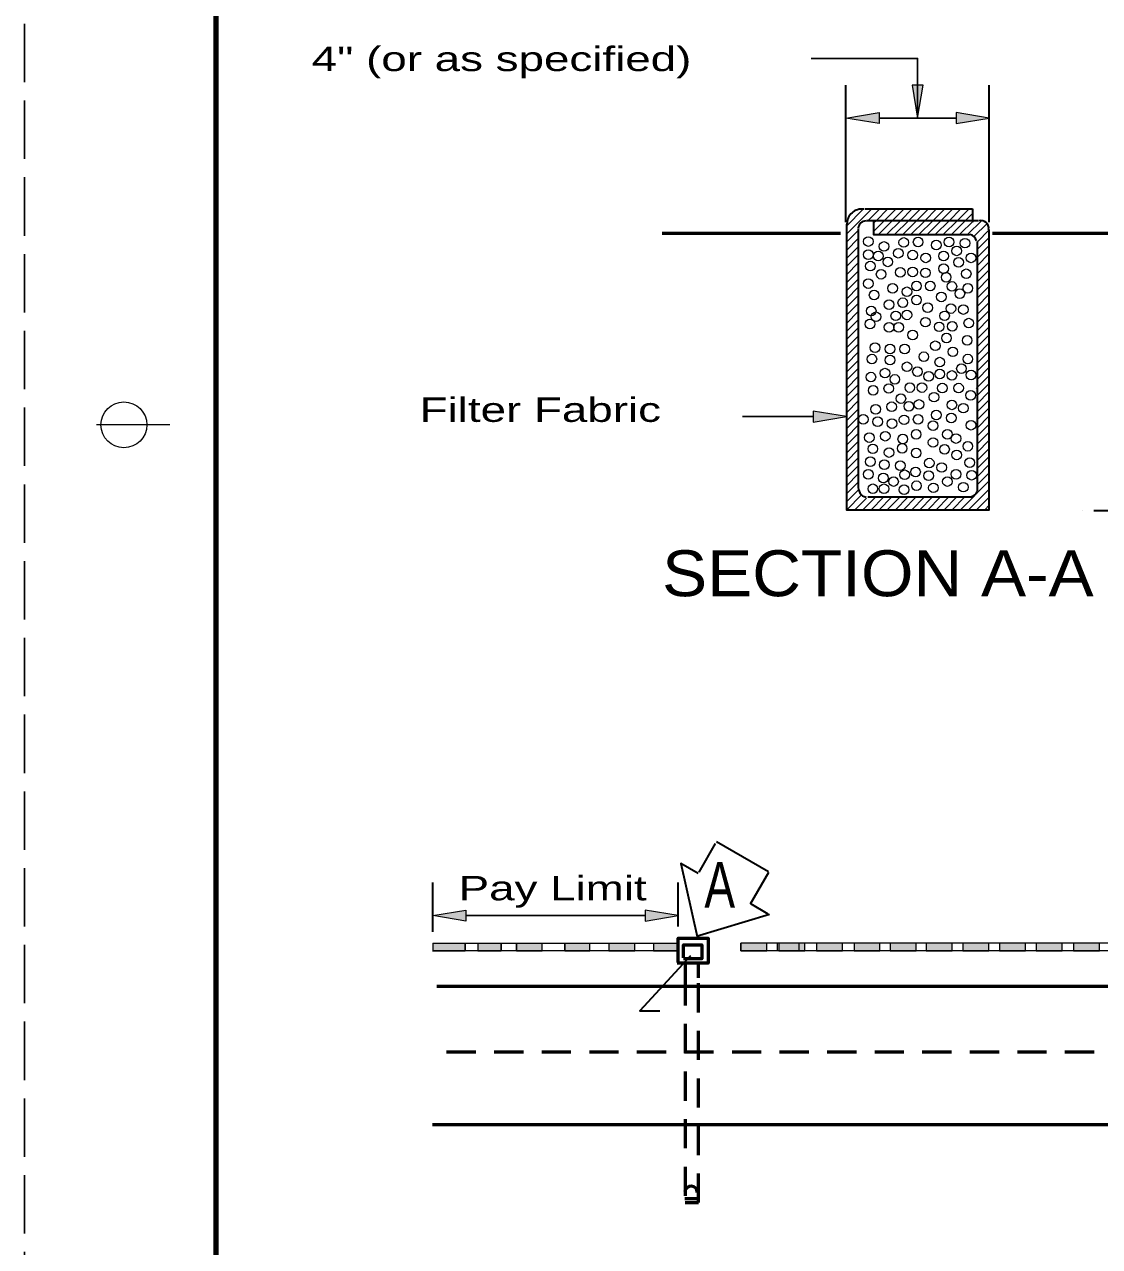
# Model space of a CAD drawing. Extents: x 36 to 71.3, y 0.3 to 22.3.
# Drawn here: x 37.55 to 43.4, y 10.65 to 17.3 of the extents above; entities that cross this region are included whole.
import ezdxf

# ---------------------------------------------------------------- set-up
doc = ezdxf.new("R2010")
doc.units = 0
doc.header["$LTSCALE"] = 0.053
doc.linetypes.add('LONG_DASHED', pattern=[7.5, 6, -1.5])
doc.linetypes.add('MEDIUM_DASHED', pattern=[4.5, 3, -1.5])
for name, color, linetype, lineweight in [('1', 7, 'Continuous', 13), ('2', 7, 'Continuous', 13), ('3', 7, 'MEDIUM_DASHED', 53), ('4', 7, 'Continuous', 13)]:
    doc.layers.add(name, color=color, linetype=linetype, lineweight=lineweight)

msp = doc.modelspace()

# ---------------------------------------------------------------- hatches: boundary and pattern name
at = {"layer": '1'}
for points in [[(42.20192, 16.82442), (42.20192, 16.76442), (42.02192, 16.79442), (42.02192, 16.79442)], [(42.62242, 16.82442), (42.62242, 16.76442), (42.80242, 16.79442), (42.80242, 16.79442)], [(39.95242, 12.48133), (39.95242, 12.42133), (39.77242, 12.45133), (39.77242, 12.45133)], [(40.92883, 12.48133), (40.92883, 12.42133), (41.10883, 12.45133), (41.10883, 12.45133)], [(39.77242, 12.25717), (39.94733, 12.25883), (39.94733, 12.3), (39.77242, 12.3)], [(40.01675, 12.25883), (40.14333, 12.25883), (40.14333, 12.3), (40.01675, 12.29758)], [(40.227, 12.25883), (40.36683, 12.25883), (40.36683, 12.3), (40.227, 12.3)], [(40.49008, 12.25883), (40.62658, 12.25883), (40.62658, 12.3), (40.49008, 12.3)], [(40.73117, 12.25883), (40.87208, 12.25883), (40.87208, 12.3), (40.73117, 12.3)], [(40.97333, 12.25883), (41.10658, 12.25883), (41.10658, 12.3), (40.97333, 12.3)], [(41.4495, 12.25992), (41.59092, 12.25992), (41.59092, 12.30192), (41.4495, 12.30192)], [(41.65583, 12.25992), (41.79725, 12.25992), (41.79725, 12.30192), (41.65583, 12.30192)], [(41.86217, 12.25992), (42.00358, 12.25992), (42.00358, 12.30192), (41.86217, 12.30192)], [(42.06558, 12.25992), (42.20692, 12.25992), (42.20692, 12.30192), (42.06558, 12.30192)], [(42.26183, 12.25992), (42.40325, 12.25992), (42.40325, 12.30192), (42.26183, 12.30192)], [(42.45817, 12.25992), (42.5995, 12.25992), (42.5995, 12.30192), (42.45817, 12.30192)], [(42.658, 12.25992), (42.79933, 12.25992), (42.79933, 12.30192), (42.658, 12.30192)], [(42.85783, 12.25992), (42.99925, 12.25992), (42.99925, 12.30192), (42.85783, 12.30192)], [(43.05758, 12.25992), (43.19908, 12.25992), (43.19908, 12.30192), (43.05758, 12.30192)], [(43.26092, 12.25992), (43.40242, 12.25992), (43.40242, 12.30192), (43.26092, 12.30192)]]:
    msp.add_hatch(color=256, dxfattribs=at).paths.add_polyline_path(points)
at = {"layer": '2'}
for points in [[(42.44217, 16.97442), (42.38217, 16.97442), (42.41217, 16.79442), (42.41217, 16.79442)], [(41.84392, 15.19867), (41.84392, 15.13867), (42.02383, 15.16867), (42.02383, 15.16867)]]:
    msp.add_hatch(color=256, dxfattribs=at).paths.add_polyline_path(points)

# ---------------------------------------------------------------- linework, layer by layer
at = {"layer": '1', "linetype": 'LONG_DASHED', "lineweight": 25}
msp.add_line((37.54825, 22.32408), (37.54825, 0.32408), dxfattribs=at)
at = {"layer": '1', "lineweight": 158}
msp.add_line((38.58992, 21.82408), (38.58992, 0.82408), dxfattribs=at)
at = {"layer": '1', "lineweight": 35}
for p, q in [((42.02192, 16.227), (42.02192, 16.97442)), ((42.80242, 16.227), (42.80242, 16.97442)), ((42.71142, 16.29858), (42.12467, 16.29858)), ((42.71142, 16.29983), (42.71142, 16.22733)), ((42.08992, 14.793), (42.08992, 16.19292)), ((42.13508, 16.2375), (42.74092, 16.2375)), ((42.73575, 16.12292), (42.73575, 14.76117)), ((42.70625, 14.72942), (42.14025, 14.72942)), ((43.37108, 14.658), (43.65075, 14.658)), ((41.5995, 12.6905), (41.31683, 12.85367)), ((41.31, 12.8435), (41.22008, 12.68775)), ((41.50267, 12.51567), (41.60258, 12.68875)), ((39.77242, 12.3625), (39.77242, 12.63133)), ((41.10883, 12.39142), (41.10883, 12.63133)), ((41.59883, 12.46008), (41.50417, 12.51475)), ((41.20808, 12.33892), (41.60467, 12.45967))]:
    msp.add_line(p, q, dxfattribs=at)
at = {"layer": '1', "lineweight": 25}
for p, q in [((42.20192, 16.79442), (42.62242, 16.79442)), ((42.73575, 15.94617), (42.80167, 16.01217)), ((39.95242, 12.45133), (40.92883, 12.45133))]:
    msp.add_line(p, q, dxfattribs=at)
at = {"layer": '1'}
for p, q in [((42.02392, 16.20667), (42.11625, 16.29892)), ((42.02392, 16.16242), (42.16008, 16.29858)), ((42.14317, 16.2375), (42.20425, 16.29858)), ((42.18742, 16.2375), (42.2485, 16.29858)), ((42.23158, 16.2375), (42.29267, 16.29858)), ((42.27575, 16.2375), (42.33683, 16.29858)), ((42.32, 16.2375), (42.38108, 16.29858)), ((42.36417, 16.2375), (42.42525, 16.29858)), ((42.40833, 16.2375), (42.46942, 16.29858)), ((42.45258, 16.2375), (42.51367, 16.29858)), ((42.49675, 16.2375), (42.55783, 16.29858)), ((42.54092, 16.2375), (42.602, 16.29858)), ((42.58517, 16.2375), (42.64625, 16.29858)), ((42.62933, 16.2375), (42.69042, 16.29858)), ((42.6735, 16.2375), (42.71142, 16.27542)), ((42.02392, 16.11825), (42.08992, 16.18425)), ((42.1715, 16.17742), (42.23158, 16.2375)), ((42.1715, 16.22158), (42.18742, 16.2375)), ((42.19817, 16.15983), (42.27575, 16.2375)), ((42.24233, 16.15983), (42.32, 16.2375)), ((42.2865, 16.15983), (42.36417, 16.2375)), ((42.33075, 16.15983), (42.40833, 16.2375)), ((42.37492, 16.15983), (42.45258, 16.2375)), ((42.41908, 16.15983), (42.49675, 16.2375)), ((42.46333, 16.15983), (42.54092, 16.2375)), ((42.5075, 16.15983), (42.58517, 16.2375)), ((42.55167, 16.15983), (42.62933, 16.2375)), ((42.59592, 16.15983), (42.6735, 16.2375)), ((42.64008, 16.15983), (42.71767, 16.2375)), ((42.68425, 16.15983), (42.76108, 16.23667)), ((42.68425, 16.15983), (42.76108, 16.23667)), ((42.71142, 16.23125), (42.71767, 16.2375)), ((42.7185, 16.14992), (42.79008, 16.22142)), ((42.7185, 16.14992), (42.79008, 16.22142)), ((42.73575, 16.1195), (42.80167, 16.18542)), ((42.02392, 16.07408), (42.08992, 16.14)), ((42.73575, 16.07875), (42.80167, 16.14475)), ((42.02392, 16.02983), (42.08992, 16.09583)), ((42.02392, 15.98567), (42.08992, 16.05167)), ((42.73575, 16.03458), (42.80167, 16.1005)), ((42.73575, 15.99033), (42.80167, 16.05633)), ((42.02392, 15.9415), (42.08992, 16.00742)), ((42.02392, 15.89725), (42.08992, 15.96325)), ((42.02392, 15.85308), (42.08992, 15.91908)), ((42.73575, 15.902), (42.80167, 15.96792)), ((42.73575, 15.85775), (42.80167, 15.92375)), ((42.02392, 15.80892), (42.08992, 15.87483)), ((42.73575, 15.81358), (42.80167, 15.87958)), ((42.02392, 15.76467), (42.08992, 15.83067)), ((42.02392, 15.7205), (42.08992, 15.7865)), ((42.73575, 15.76942), (42.80167, 15.83533)), ((42.73575, 15.72517), (42.80167, 15.79117)), ((42.02392, 15.67633), (42.08992, 15.74225)), ((42.73575, 15.681), (42.80167, 15.747)), ((42.02392, 15.63208), (42.08992, 15.69808)), ((42.02392, 15.58792), (42.08992, 15.65392)), ((42.73575, 15.63683), (42.80167, 15.70275)), ((42.73575, 15.59258), (42.80167, 15.65858)), ((42.02392, 15.54375), (42.08992, 15.60967)), ((42.73575, 15.54842), (42.80167, 15.61442)), ((42.02392, 15.4995), (42.08992, 15.5655)), ((42.02392, 15.45533), (42.08992, 15.52133)), ((42.73575, 15.50425), (42.80167, 15.57017)), ((42.73575, 15.46), (42.80167, 15.526)), ((42.02392, 15.41117), (42.08992, 15.47708)), ((42.73575, 15.41583), (42.80167, 15.48183)), ((42.02392, 15.36692), (42.08992, 15.43292)), ((42.02392, 15.32275), (42.08992, 15.38875)), ((42.7305, 15.32217), (42.80167, 15.39342)), ((42.73575, 15.37167), (42.80167, 15.43758)), ((42.02392, 15.27858), (42.08992, 15.3445)), ((42.73575, 15.28325), (42.80167, 15.34925)), ((42.02392, 15.23433), (42.08992, 15.30033)), ((42.02392, 15.19017), (42.08992, 15.25617)), ((42.73575, 15.23908), (42.80167, 15.305)), ((42.73575, 15.19483), (42.80167, 15.26083)), ((42.02392, 15.146), (42.08992, 15.21192)), ((42.73575, 15.15067), (42.80167, 15.21667)), ((38.33992, 15.12408), (37.93992, 15.12408)), ((42.02392, 15.10175), (42.08992, 15.16775)), ((42.02392, 15.05758), (42.08992, 15.12358)), ((42.73575, 15.1065), (42.80167, 15.17242)), ((42.73575, 15.06225), (42.80167, 15.12825)), ((42.02392, 15.01342), (42.08992, 15.07933)), ((42.73575, 15.01808), (42.80167, 15.08408)), ((42.02392, 14.96917), (42.08992, 15.03517)), ((42.02392, 14.925), (42.08992, 14.991)), ((42.73575, 14.97392), (42.80167, 15.03983)), ((42.73575, 14.92967), (42.80167, 14.99567)), ((42.02392, 14.88083), (42.08992, 14.94675)), ((42.73575, 14.8855), (42.80167, 14.9515)), ((42.02392, 14.83658), (42.08992, 14.90258)), ((42.02392, 14.79242), (42.08992, 14.85842)), ((42.73575, 14.84133), (42.80167, 14.90725)), ((42.73575, 14.79708), (42.80167, 14.86308)), ((42.02392, 14.74825), (42.08992, 14.81417)), ((42.64475, 14.66192), (42.80167, 14.81892)), ((42.02392, 14.704), (42.09, 14.77017)), ((42.026, 14.66192), (42.10692, 14.74283)), ((42.07025, 14.66192), (42.13367, 14.72533)), ((42.11442, 14.66192), (42.18192, 14.72942)), ((42.15858, 14.66192), (42.22608, 14.72942)), ((42.20283, 14.66192), (42.27025, 14.72942)), ((42.247, 14.66192), (42.3145, 14.72942)), ((42.29117, 14.66192), (42.35867, 14.72942)), ((42.33542, 14.66192), (42.40283, 14.72942)), ((42.37958, 14.66192), (42.44708, 14.72942)), ((42.42375, 14.66192), (42.49125, 14.72942)), ((42.468, 14.66192), (42.53542, 14.72942)), ((42.51217, 14.66192), (42.57958, 14.72942)), ((42.55633, 14.66192), (42.62383, 14.72942)), ((42.60058, 14.66192), (42.668, 14.72942)), ((42.68892, 14.66192), (42.80167, 14.77467)), ((42.73317, 14.66192), (42.80167, 14.7305)), ((42.77733, 14.66192), (42.80167, 14.68633)), ((39.94908, 12.25892), (39.94908, 12.30092)), ((40.0185, 12.25892), (40.0185, 12.30092)), ((40.14525, 12.25892), (40.14525, 12.30092)), ((40.22858, 12.25892), (40.22858, 12.30092)), ((40.3675, 12.25892), (40.3675, 12.30092)), ((40.49075, 12.25892), (40.49075, 12.30092)), ((40.62792, 12.25892), (40.62792, 12.30092)), ((40.73208, 12.25892), (40.73208, 12.30092)), ((40.87267, 12.25892), (40.87267, 12.30092)), ((40.97517, 12.25892), (40.97517, 12.30092)), ((44.00117, 12.26017), (41.44908, 12.26017)), ((41.44958, 12.25892), (41.44958, 12.30092)), ((43.99767, 12.30217), (41.45258, 12.30217)), ((41.59075, 12.25892), (41.59075, 12.30092)), ((41.64983, 12.25892), (41.64983, 12.30092)), ((41.767, 12.25892), (41.767, 12.30092))]:
    msp.add_line(p, q, dxfattribs=at)
at = {"layer": '1', "lineweight": 53}
for p, q in [((41.0205, 16.16875), (41.99267, 16.16875)), ((42.81908, 16.16875), (43.91108, 16.16875)), ((39.79458, 12.068), (49.87267, 12.068)), ((39.77025, 11.31333), (49.87267, 11.31333)), ((41.1435, 10.91117), (41.21817, 10.91117)), ((41.147, 10.88825), (41.21817, 10.88825))]:
    msp.add_line(p, q, dxfattribs=at)
at = {"layer": '1'}
for points in [[(42.20192, 16.82442), (42.20192, 16.76442), (42.02192, 16.79442), (42.02192, 16.79442)], [(42.62242, 16.82442), (42.62242, 16.76442), (42.80242, 16.79442), (42.80242, 16.79442)], [(39.95242, 12.48133), (39.95242, 12.42133), (39.77242, 12.45133), (39.77242, 12.45133)], [(40.92883, 12.48133), (40.92883, 12.42133), (41.10883, 12.45133), (41.10883, 12.45133)], [(39.77242, 12.25717), (39.94733, 12.25883), (39.94733, 12.3), (39.77242, 12.3)], [(40.01675, 12.25883), (40.14333, 12.25883), (40.14333, 12.3), (40.01675, 12.29758)], [(40.227, 12.25883), (40.36683, 12.25883), (40.36683, 12.3), (40.227, 12.3)], [(40.49008, 12.25883), (40.62658, 12.25883), (40.62658, 12.3), (40.49008, 12.3)], [(40.73117, 12.25883), (40.87208, 12.25883), (40.87208, 12.3), (40.73117, 12.3)], [(40.97333, 12.25883), (41.10658, 12.25883), (41.10658, 12.3), (40.97333, 12.3)], [(41.4495, 12.25992), (41.59092, 12.25992), (41.59092, 12.30192), (41.4495, 12.30192)], [(41.65583, 12.25992), (41.79725, 12.25992), (41.79725, 12.30192), (41.65583, 12.30192)], [(41.86217, 12.25992), (42.00358, 12.25992), (42.00358, 12.30192), (41.86217, 12.30192)], [(42.06558, 12.25992), (42.20692, 12.25992), (42.20692, 12.30192), (42.06558, 12.30192)], [(42.26183, 12.25992), (42.40325, 12.25992), (42.40325, 12.30192), (42.26183, 12.30192)], [(42.45817, 12.25992), (42.5995, 12.25992), (42.5995, 12.30192), (42.45817, 12.30192)], [(42.658, 12.25992), (42.79933, 12.25992), (42.79933, 12.30192), (42.658, 12.30192)], [(42.85783, 12.25992), (42.99925, 12.25992), (42.99925, 12.30192), (42.85783, 12.30192)], [(43.05758, 12.25992), (43.19908, 12.25992), (43.19908, 12.30192), (43.05758, 12.30192)], [(43.26092, 12.25992), (43.40242, 12.25992), (43.40242, 12.30192), (43.26092, 12.30192)]]:
    msp.add_lwpolyline(points, close=True, dxfattribs=at)
at = {"layer": '1', "lineweight": 35}
for points in [[(42.02392, 16.21717), (42.02392, 14.66192), (42.80167, 14.66192), (42.80167, 16.18783)], [(42.1715, 16.23242), (42.1715, 16.15983), (42.69408, 16.15983)], [(41.21692, 12.68058), (41.12225, 12.73525), (41.21175, 12.33825)], [(41.17475, 12.23217), (40.89875, 11.93308), (41.00808, 11.93308)]]:
    msp.add_lwpolyline(points, dxfattribs=at)
at = {"layer": '1', "lineweight": 53}
for points in [[(41.10883, 12.19525), (41.10883, 12.32892), (41.272, 12.32892), (41.272, 12.19275), (41.10183, 12.19275)], [(41.13658, 12.22075), (41.13658, 12.292), (41.23725, 12.292), (41.23725, 12.21567), (41.13658, 12.21567)]]:
    msp.add_lwpolyline(points, dxfattribs=at)
at = {"layer": '1'}
msp.add_lwpolyline([(41.10183, 12.25892), (39.77375, 12.25892), (39.77375, 12.30092), (41.10708, 12.30092)], dxfattribs=at)
for centre, radius in [((42.14375, 16.12233), 0.02615), ((42.22883, 16.09558), 0.02615), ((42.33642, 16.11725), 0.02615), ((42.41458, 16.11975), 0.02615), ((42.5135, 16.10325), 0.02615), ((42.58292, 16.11975), 0.02615), ((42.66975, 16.11342), 0.02615), ((42.14375, 16.05108), 0.02615), ((42.19758, 16.04342), 0.02615), ((42.30692, 16.05867), 0.02615), ((42.385, 16.0485), 0.02615), ((42.45625, 16.03325), 0.02615), ((42.55342, 16.04342), 0.02615), ((42.62458, 16.07142), 0.02615), ((42.70275, 16.03325), 0.02615), ((42.15417, 15.98867), 0.02615), ((42.24967, 16.01158), 0.02615), ((42.31733, 15.95433), 0.02615), ((42.385, 15.95683), 0.02615), ((42.4545, 15.95175), 0.02615), ((42.55342, 15.97467), 0.02615), ((42.635, 16.00908), 0.02615), ((42.14375, 15.89325), 0.02615), ((42.21317, 15.94417), 0.02615), ((42.40583, 15.8805), 0.02615), ((42.4805, 15.8805), 0.02615), ((42.56733, 15.92758), 0.02615), ((42.67667, 15.94667), 0.02615), ((42.175, 15.83083), 0.02615), ((42.27567, 15.86775), 0.02615), ((42.35375, 15.84867), 0.02615), ((42.54125, 15.82067), 0.02615), ((42.59858, 15.878), 0.02615), ((42.642, 15.8385), 0.02615), ((42.68542, 15.86775), 0.02615), ((42.25658, 15.77867), 0.02615), ((42.33125, 15.78892), 0.02615), ((42.40583, 15.80417), 0.02615), ((42.46667, 15.76217), 0.02615), ((42.59333, 15.75708), 0.02615), ((42.66108, 15.752), 0.02615), ((42.15933, 15.74433), 0.02615), ((42.18542, 15.7125), 0.02615), ((42.293, 15.71758), 0.02615), ((42.35375, 15.72267), 0.02615), ((42.4545, 15.68325), 0.02615), ((42.55867, 15.71758), 0.02615), ((42.15242, 15.67308), 0.02615), ((42.25658, 15.65525), 0.02615), ((42.30867, 15.65525), 0.02615), ((42.52917, 15.65783), 0.02615), ((42.60033, 15.66033), 0.02615), ((42.69058, 15.67817), 0.02615), ((42.385, 15.61325), 0.02615), ((42.50833, 15.55467), 0.02615), ((42.56908, 15.59667), 0.02615), ((42.68192, 15.584), 0.02615), ((42.16283, 15.48217), 0.02615), ((42.18017, 15.5445), 0.02615), ((42.26175, 15.53692), 0.02615), ((42.34167, 15.53692), 0.02615), ((42.44583, 15.49492), 0.02615), ((42.60375, 15.52158), 0.02615), ((42.68542, 15.48217), 0.02615), ((42.26175, 15.47708), 0.02615), ((42.35375, 15.44017), 0.02615), ((42.53258, 15.46558), 0.02615), ((42.65067, 15.43), 0.02615), ((42.15758, 15.38417), 0.02615), ((42.234, 15.40583), 0.02615), ((42.28783, 15.37142), 0.02615), ((42.41108, 15.41342), 0.02615), ((42.47183, 15.388), 0.02615), ((42.53258, 15.40075), 0.02615), ((42.59858, 15.39308), 0.02615), ((42.70275, 15.39558), 0.02615), ((42.16975, 15.31167), 0.02615), ((42.25483, 15.32183), 0.02615), ((42.36942, 15.32692), 0.02615), ((42.43542, 15.32692), 0.02615), ((42.5465, 15.32433), 0.02615), ((42.635, 15.32433), 0.02615), ((42.701, 15.28492), 0.02615), ((38.08992, 15.12408), 0.125), ((42.2705, 15.22258), 0.02615), ((42.32083, 15.26708), 0.02615), ((42.36425, 15.22508), 0.02615), ((42.41975, 15.23525), 0.02615), ((42.50133, 15.27475), 0.02615), ((42.59858, 15.23275), 0.02615), ((42.66108, 15.21492), 0.02615), ((42.11592, 15.15383), 0.02615), ((42.18367, 15.20858), 0.02615), ((42.33817, 15.15125), 0.02615), ((42.41458, 15.15383), 0.02615), ((42.5135, 15.178), 0.02615), ((42.59508, 15.16142), 0.02615), ((42.19408, 15.14108), 0.02615), ((42.27217, 15.13092), 0.02615), ((42.49617, 15.11942), 0.02615), ((42.70275, 15.122), 0.02615), ((42.14892, 15.05458), 0.02615), ((42.23575, 15.06217), 0.02615), ((42.33125, 15.04692), 0.02615), ((42.40417, 15.07233), 0.02615), ((42.49617, 15.02783), 0.02615), ((42.57425, 15.07233), 0.02615), ((42.62117, 15.0495), 0.02615), ((42.168, 14.9935), 0.02615), ((42.25658, 14.97308), 0.02615), ((42.32775, 14.996), 0.02615), ((42.40417, 14.97058), 0.02615), ((42.55867, 14.99092), 0.02615), ((42.62458, 14.96033), 0.02615), ((42.68542, 15.0075), 0.02615), ((42.15417, 14.9235), 0.02615), ((42.2305, 14.90692), 0.02615), ((42.31733, 14.90183), 0.02615), ((42.47533, 14.91583), 0.02615), ((42.543, 14.89167), 0.02615), ((42.69583, 14.91842), 0.02615), ((42.14375, 14.85475), 0.02615), ((42.22533, 14.83442), 0.02615), ((42.34167, 14.85217), 0.02615), ((42.40067, 14.8675), 0.02615), ((42.47183, 14.84708), 0.02615), ((42.62117, 14.85475), 0.02615), ((42.70625, 14.84967), 0.02615), ((42.168, 14.77583), 0.02615), ((42.22883, 14.77583), 0.02615), ((42.28092, 14.81525), 0.02615), ((42.33817, 14.77075), 0.02615), ((42.40583, 14.79242), 0.02615), ((42.49792, 14.78092), 0.02615), ((42.57425, 14.81525), 0.02615), ((42.66108, 14.78475), 0.02615)]:
    msp.add_circle(centre, radius, dxfattribs=at)
at = {"layer": '1', "lineweight": 35}
for centre, radius, start, end in [((42.10842, 16.21825), 0.08105, 82.22224, 180.80819), ((42.13192, 16.19092), 0.04402, 90.49302, 174.04793), ((42.75817, 16.19592), 0.04087, 348.68321, 107.08322), ((42.69108, 16.11833), 0.0418, 9.87382, 83.51724), ((42.14667, 14.78625), 0.05886, 173.43227, 255.16171), ((42.69717, 14.77567), 0.04216, 282.42627, 336.22905)]:
    msp.add_arc(centre, radius, start, end, dxfattribs=at)
at = {"layer": '1', "lineweight": 53}
msp.add_arc((41.178, 10.94367), 0.03496, 0.97484, 170.63996, dxfattribs=at)
at = {"layer": '2', "lineweight": 25}
msp.add_line((41.84392, 15.16867), (41.45858, 15.16867), dxfattribs=at)
msp.add_lwpolyline([(42.41217, 16.79442), (42.41217, 17.11958), (41.83233, 17.11958)], dxfattribs=at)
at = {"layer": '2'}
for points in [[(42.44217, 16.97442), (42.38217, 16.97442), (42.41217, 16.79442), (42.41217, 16.79442)], [(41.84392, 15.19867), (41.84392, 15.13867), (42.02383, 15.16867), (42.02383, 15.16867)]]:
    msp.add_lwpolyline(points, close=True, dxfattribs=at)
at = {"layer": '3'}
for p, q in [((41.21817, 12.11233), (41.21817, 12.19017)), ((41.21817, 10.88825), (41.21817, 12.12325)), ((49.84833, 11.70783), (39.77025, 11.70783))]:
    msp.add_line(p, q, dxfattribs=at)
msp.add_lwpolyline([(41.147, 12.19017), (41.147, 12.12025), (41.147, 10.88825)], dxfattribs=at)
at = {"layer": '4'}
for p, q in [((42.80242, 16.79442), (42.8025, 16.79442)), ((42.02192, 16.1645), (42.022, 16.1645)), ((42.80242, 16.1645), (42.8025, 16.1645)), ((43.34125, 16.16875), (43.34133, 16.16875)), ((43.30858, 14.658), (43.30867, 14.658)), ((41.10883, 12.45133), (41.10892, 12.45133)), ((41.10883, 12.32892), (41.10892, 12.32892)), ((39.77242, 12.3), (39.7725, 12.3))]:
    msp.add_line(p, q, dxfattribs=at)

# ---------------------------------------------------------------- texts
at = {"layer": '2'}
for s, height, width, p in [('4" (or as specified)', 0.133, 1.4, (39.11267, 17.05058)), ('Filter Fabric', 0.133, 1.4, (39.70025, 15.14008)), ('SECTION A-A', 0.25, 1.1, (41.02058, 14.19083)), ('A', 0.25, 0.75, (41.25075, 12.49425)), ('Pay Limit', 0.133, 1.4, (39.91242, 12.53458))]:
    msp.add_text(s, height=height, dxfattribs=dict(at, width=width)).set_placement(p)

doc.saveas('drawing.dxf')
